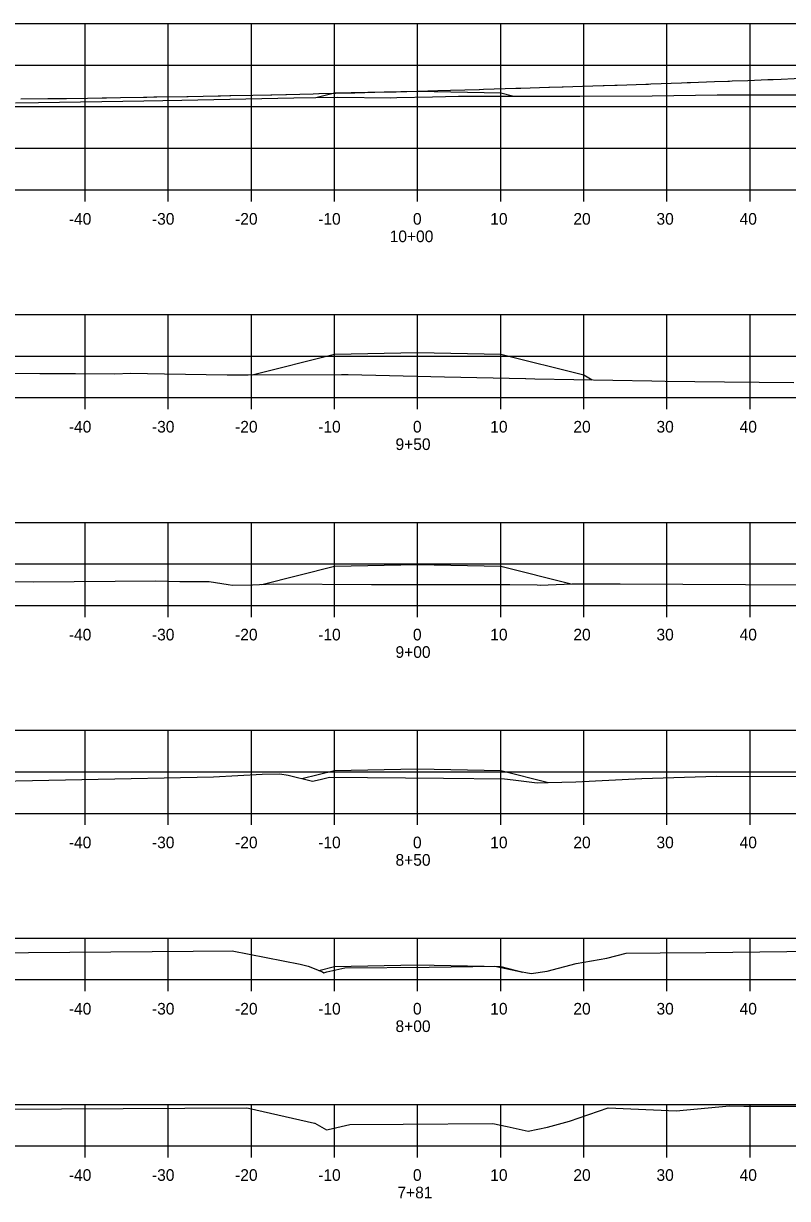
# Model space of a CAD drawing. Extents: x 1098669 to 1198896, y 698679 to 704410.
# Drawn here: x 1110733.7 to 1110825.7, y 701502.8 to 701644.1 of the extents above; entities that cross this region are included whole.
import ezdxf

# ---------------------------------------------------------------- set-up
doc = ezdxf.new("R2010")
doc.units = 0
for name, color, linetype in [('Proposed Surface', 7, 'Continuous'), ('R_Axis', 7, 'Continuous'), ('R_Axis Annot', 7, 'Continuous'), ('R_Fin Surface', 7, 'Continuous'), ('R_Grid', 7, 'Continuous')]:
    doc.layers.add(name, color=color, linetype=linetype)

msp = doc.modelspace()

# ---------------------------------------------------------------- linework, layer by layer
at = {"layer": 'Proposed Surface'}
for points in [[(1110732.78, 701634.57), (1110735.56, 701634.61), (1110748.22, 701634.82), (1110752.79, 701634.89), (1110766.27, 701635.19), (1110771.58, 701635.26), (1110777.92, 701635.2), (1110778.68, 701635.23), (1110782.94, 701635.31), (1110784.51, 701635.36), (1110786.08, 701635.39), (1110800.69, 701635.4), (1110809.37, 701635.44), (1110817.22, 701635.54), (1110827.92, 701635.53)], [(1110730.48, 701602.06), (1110735.69, 701602.04), (1110740, 701602.04), (1110744.73, 701602.01), (1110746.62, 701602.06), (1110750.72, 701602), (1110758.26, 701601.87), (1110760.79, 701601.89), (1110772.02, 701601.92), (1110772.62, 701601.92), (1110772.79, 701601.93), (1110784.41, 701601.64), (1110794.15, 701601.42), (1110794.19, 701601.42), (1110795.28, 701601.39), (1110809.35, 701601.16), (1110810.93, 701601.11), (1110818.1, 701601.03), (1110826.42, 701600.95)], [(1110727.68, 701577.01), (1110734.95, 701576.99), (1110749.68, 701577.08), (1110752.54, 701577.03), (1110755.55, 701577.02), (1110756.07, 701577.01), (1110758.37, 701576.64), (1110758.89, 701576.58), (1110761.28, 701576.62), (1110763.79, 701576.72), (1110775.63, 701576.64), (1110792.24, 701576.64), (1110795.54, 701576.61), (1110795.89, 701576.57), (1110799.77, 701576.74), (1110800.16, 701576.74), (1110805.54, 701576.75), (1110828.16, 701576.6)], [(1110724.88, 701552.88), (1110756.59, 701553.51), (1110762.45, 701553.84), (1110764.58, 701553.88), (1110765.57, 701553.71), (1110768.53, 701553), (1110769.44, 701553.21), (1110770.57, 701553.5), (1110784.28, 701553.37), (1110791.63, 701553.29), (1110792.67, 701553.18), (1110795.53, 701552.8), (1110796.84, 701552.85), (1110800.19, 701552.92), (1110808.12, 701553.34), (1110817.14, 701553.61), (1110838.07, 701553.53)], [(1110719.46, 701532.28), (1110754.17, 701532.55), (1110758.84, 701532.58), (1110767.03, 701530.99), (1110768.01, 701530.77), (1110769.7, 701530.05), (1110769.86, 701529.95), (1110770.25, 701530.05), (1110772.42, 701530.54), (1110782.55, 701530.62), (1110790.44, 701530.74), (1110793.08, 701530.17), (1110794.83, 701529.85), (1110796.73, 701530.16), (1110800.25, 701531.09), (1110803.92, 701531.73), (1110806.26, 701532.32), (1110810.35, 701532.36), (1110815.83, 701532.41), (1110825.58, 701532.51), (1110837.52, 701532.63)], [(1110723.44, 701513.53), (1110760.56, 701513.71), (1110760.83, 701513.66), (1110768.77, 701511.86), (1110768.81, 701511.85), (1110770.21, 701511.05), (1110770.4, 701511.09), (1110772.99, 701511.71), (1110779.41, 701511.74), (1110790.23, 701511.82), (1110791.94, 701511.45), (1110794.45, 701510.89), (1110796.78, 701511.4), (1110799.45, 701512.11), (1110804.08, 701513.7), (1110812.26, 701513.35), (1110818.69, 701513.94), (1110820.41, 701513.93), (1110832.6, 701513.91)]]:
    msp.add_lwpolyline(points, dxfattribs=at)
at = {"layer": 'R_Axis'}
for p, q in [((1110641.16, 701624.13), (1110921.16, 701624.13)), ((1110741.16, 701622.73), (1110741.16, 701624.13)), ((1110751.16, 701622.73), (1110751.16, 701624.13)), ((1110761.16, 701622.73), (1110761.16, 701624.13)), ((1110771.16, 701622.73), (1110771.16, 701624.13)), ((1110781.16, 701622.73), (1110781.16, 701624.13)), ((1110791.16, 701622.73), (1110791.16, 701624.13)), ((1110801.16, 701622.73), (1110801.16, 701624.13)), ((1110811.16, 701622.73), (1110811.16, 701624.13)), ((1110821.16, 701622.73), (1110821.16, 701624.13)), ((1110641.16, 701599.13), (1110921.16, 701599.13)), ((1110741.16, 701597.73), (1110741.16, 701599.13)), ((1110751.16, 701597.73), (1110751.16, 701599.13)), ((1110761.16, 701597.73), (1110761.16, 701599.13)), ((1110771.16, 701597.73), (1110771.16, 701599.13)), ((1110781.16, 701597.73), (1110781.16, 701599.13)), ((1110791.16, 701597.73), (1110791.16, 701599.13)), ((1110801.16, 701597.73), (1110801.16, 701599.13)), ((1110811.16, 701597.73), (1110811.16, 701599.13)), ((1110821.16, 701597.73), (1110821.16, 701599.13)), ((1110641.16, 701574.13), (1110921.16, 701574.13)), ((1110741.16, 701572.73), (1110741.16, 701574.13)), ((1110751.16, 701572.73), (1110751.16, 701574.13)), ((1110761.16, 701572.73), (1110761.16, 701574.13)), ((1110771.16, 701572.73), (1110771.16, 701574.13)), ((1110781.16, 701572.73), (1110781.16, 701574.13)), ((1110791.16, 701572.73), (1110791.16, 701574.13)), ((1110801.16, 701572.73), (1110801.16, 701574.13)), ((1110811.16, 701572.73), (1110811.16, 701574.13)), ((1110821.16, 701572.73), (1110821.16, 701574.13)), ((1110641.16, 701549.13), (1110921.16, 701549.13)), ((1110741.16, 701547.73), (1110741.16, 701549.13)), ((1110751.16, 701547.73), (1110751.16, 701549.13)), ((1110761.16, 701547.73), (1110761.16, 701549.13)), ((1110771.16, 701547.73), (1110771.16, 701549.13)), ((1110781.16, 701547.73), (1110781.16, 701549.13)), ((1110791.16, 701547.73), (1110791.16, 701549.13)), ((1110801.16, 701547.73), (1110801.16, 701549.13)), ((1110811.16, 701547.73), (1110811.16, 701549.13)), ((1110821.16, 701547.73), (1110821.16, 701549.13)), ((1110641.16, 701529.13), (1110921.16, 701529.13)), ((1110741.16, 701527.73), (1110741.16, 701529.13)), ((1110751.16, 701527.73), (1110751.16, 701529.13)), ((1110761.16, 701527.73), (1110761.16, 701529.13)), ((1110771.16, 701527.73), (1110771.16, 701529.13)), ((1110781.16, 701527.73), (1110781.16, 701529.13)), ((1110791.16, 701527.73), (1110791.16, 701529.13)), ((1110801.16, 701527.73), (1110801.16, 701529.13)), ((1110811.16, 701527.73), (1110811.16, 701529.13)), ((1110821.16, 701527.73), (1110821.16, 701529.13)), ((1110641.16, 701509.13), (1110921.16, 701509.13)), ((1110741.16, 701507.73), (1110741.16, 701509.13)), ((1110751.16, 701507.73), (1110751.16, 701509.13)), ((1110761.16, 701507.73), (1110761.16, 701509.13)), ((1110771.16, 701507.73), (1110771.16, 701509.13)), ((1110781.16, 701507.73), (1110781.16, 701509.13)), ((1110791.16, 701507.73), (1110791.16, 701509.13)), ((1110801.16, 701507.73), (1110801.16, 701509.13)), ((1110811.16, 701507.73), (1110811.16, 701509.13)), ((1110821.16, 701507.73), (1110821.16, 701509.13))]:
    msp.add_line(p, q, dxfattribs=at)
at = {"layer": 'R_Fin Surface'}
for points in [[(1110733.41, 701635.05), (1110736.68, 701635.09), (1110737.43, 701635.1), (1110738.24, 701635.11), (1110738.42, 701635.11), (1110738.93, 701635.12), (1110741.43, 701635.16), (1110743.19, 701635.19), (1110743.47, 701635.19), (1110743.73, 701635.19), (1110745.43, 701635.22), (1110748.19, 701635.27), (1110748.51, 701635.27), (1110748.6, 701635.27), (1110749.42, 701635.29), (1110749.79, 701635.29), (1110753.4, 701635.36), (1110753.53, 701635.36), (1110753.54, 701635.36), (1110757.17, 701635.43), (1110757.38, 701635.44), (1110757.44, 701635.44), (1110758.56, 701635.46), (1110758.7, 701635.46), (1110761.35, 701635.52), (1110763.51, 701635.56), (1110763.58, 701635.56), (1110763.63, 701635.56), (1110765.32, 701635.6), (1110765.39, 701635.6), (1110768.58, 701635.68), (1110769.27, 701635.69), (1110769.28, 701635.69), (1110769.33, 701635.69), (1110773.24, 701635.79), (1110773.58, 701635.8), (1110773.59, 701635.8), (1110777.2, 701635.89), (1110777.2, 701635.89), (1110777.21, 701635.89), (1110778.59, 701635.92), (1110781.16, 701635.99), (1110783.59, 701636.06), (1110783.59, 701636.06), (1110783.59, 701636.06), (1110785.12, 701636.1), (1110788.57, 701636.2), (1110788.59, 701636.2), (1110788.59, 701636.2), (1110789.08, 701636.21), (1110792.99, 701636.33), (1110793.04, 701636.33), (1110793.05, 701636.33), (1110793.59, 701636.35), (1110796.93, 701636.45), (1110797.01, 701636.46), (1110798.55, 701636.51), (1110798.6, 701636.51), (1110798.67, 701636.51), (1110800.98, 701636.58), (1110803.49, 701636.67), (1110803.61, 701636.67), (1110804.88, 701636.71), (1110804.95, 701636.72), (1110805.15, 701636.72), (1110808.63, 701636.84), (1110808.9, 701636.85), (1110808.93, 701636.85), (1110809.22, 701636.86), (1110812.91, 701637), (1110813.59, 701637.02), (1110813.66, 701637.02), (1110813.99, 701637.04), (1110816.9, 701637.14), (1110818.47, 701637.2), (1110818.7, 701637.21), (1110819, 701637.22), (1110820.89, 701637.29), (1110823.28, 701637.39), (1110823.76, 701637.41), (1110823.95, 701637.41), (1110824.9, 701637.45), (1110828.01, 701637.58)], [(1110768.9, 701635.23), (1110771.16, 701635.79), (1110781.16, 701635.99), (1110791.16, 701635.79), (1110792.75, 701635.39)], [(1110761.27, 701601.89), (1110771.16, 701604.37), (1110781.16, 701604.57), (1110791.16, 701604.37), (1110801.16, 701601.87), (1110802.16, 701601.28)], [(1110762.42, 701576.66), (1110771.16, 701578.85), (1110781.16, 701579.05), (1110791.16, 701578.85), (1110799.63, 701576.73)], [(1110767.23, 701553.31), (1110771.16, 701554.29), (1110781.16, 701554.49), (1110791.16, 701554.29), (1110796.92, 701552.85)], [(1110769.27, 701530.23), (1110771.16, 701530.7), (1110781.16, 701530.9), (1110791.16, 701530.7), (1110793.79, 701530.04)]]:
    msp.add_lwpolyline(points, dxfattribs=at)
at = {"layer": 'R_Grid'}
for p, q in [((1110641.16, 701644.13), (1110921.16, 701644.13)), ((1110741.16, 701624.13), (1110741.16, 701644.13)), ((1110751.16, 701624.13), (1110751.16, 701644.13)), ((1110761.16, 701624.13), (1110761.16, 701644.13)), ((1110771.16, 701624.13), (1110771.16, 701644.13)), ((1110781.16, 701624.13), (1110781.16, 701644.13)), ((1110791.16, 701624.13), (1110791.16, 701644.13)), ((1110801.16, 701624.13), (1110801.16, 701644.13)), ((1110811.16, 701624.13), (1110811.16, 701644.13)), ((1110821.16, 701624.13), (1110821.16, 701644.13)), ((1110641.16, 701639.13), (1110921.16, 701639.13)), ((1110641.16, 701634.13), (1110921.16, 701634.13)), ((1110641.16, 701629.13), (1110921.16, 701629.13)), ((1110641.16, 701624.13), (1110921.16, 701624.13)), ((1110641.16, 701609.13), (1110921.16, 701609.13)), ((1110741.16, 701599.13), (1110741.16, 701609.13)), ((1110751.16, 701599.13), (1110751.16, 701609.13)), ((1110761.16, 701599.13), (1110761.16, 701609.13)), ((1110771.16, 701599.13), (1110771.16, 701609.13)), ((1110781.16, 701599.13), (1110781.16, 701609.13)), ((1110791.16, 701599.13), (1110791.16, 701609.13)), ((1110801.16, 701599.13), (1110801.16, 701609.13)), ((1110811.16, 701599.13), (1110811.16, 701609.13)), ((1110821.16, 701599.13), (1110821.16, 701609.13)), ((1110641.16, 701604.13), (1110921.16, 701604.13)), ((1110641.16, 701599.13), (1110921.16, 701599.13)), ((1110641.16, 701584.13), (1110921.16, 701584.13)), ((1110741.16, 701574.13), (1110741.16, 701584.13)), ((1110751.16, 701574.13), (1110751.16, 701584.13)), ((1110761.16, 701574.13), (1110761.16, 701584.13)), ((1110771.16, 701574.13), (1110771.16, 701584.13)), ((1110781.16, 701574.13), (1110781.16, 701584.13)), ((1110791.16, 701574.13), (1110791.16, 701584.13)), ((1110801.16, 701574.13), (1110801.16, 701584.13)), ((1110811.16, 701574.13), (1110811.16, 701584.13)), ((1110821.16, 701574.13), (1110821.16, 701584.13)), ((1110641.16, 701579.13), (1110921.16, 701579.13)), ((1110641.16, 701574.13), (1110921.16, 701574.13)), ((1110641.16, 701559.13), (1110921.16, 701559.13)), ((1110741.16, 701549.13), (1110741.16, 701559.13)), ((1110751.16, 701549.13), (1110751.16, 701559.13)), ((1110761.16, 701549.13), (1110761.16, 701559.13)), ((1110771.16, 701549.13), (1110771.16, 701559.13)), ((1110781.16, 701549.13), (1110781.16, 701559.13)), ((1110791.16, 701549.13), (1110791.16, 701559.13)), ((1110801.16, 701549.13), (1110801.16, 701559.13)), ((1110811.16, 701549.13), (1110811.16, 701559.13)), ((1110821.16, 701549.13), (1110821.16, 701559.13)), ((1110641.16, 701554.13), (1110921.16, 701554.13)), ((1110641.16, 701549.13), (1110921.16, 701549.13)), ((1110641.16, 701534.13), (1110921.16, 701534.13)), ((1110741.16, 701529.13), (1110741.16, 701534.13)), ((1110751.16, 701529.13), (1110751.16, 701534.13)), ((1110761.16, 701529.13), (1110761.16, 701534.13)), ((1110771.16, 701529.13), (1110771.16, 701534.13)), ((1110781.16, 701529.13), (1110781.16, 701534.13)), ((1110791.16, 701529.13), (1110791.16, 701534.13)), ((1110801.16, 701529.13), (1110801.16, 701534.13)), ((1110811.16, 701529.13), (1110811.16, 701534.13)), ((1110821.16, 701529.13), (1110821.16, 701534.13)), ((1110641.16, 701529.13), (1110921.16, 701529.13)), ((1110641.16, 701514.13), (1110921.16, 701514.13)), ((1110741.16, 701509.13), (1110741.16, 701514.13)), ((1110751.16, 701509.13), (1110751.16, 701514.13)), ((1110761.16, 701509.13), (1110761.16, 701514.13)), ((1110771.16, 701509.13), (1110771.16, 701514.13)), ((1110781.16, 701509.13), (1110781.16, 701514.13)), ((1110791.16, 701509.13), (1110791.16, 701514.13)), ((1110801.16, 701509.13), (1110801.16, 701514.13)), ((1110811.16, 701509.13), (1110811.16, 701514.13)), ((1110821.16, 701509.13), (1110821.16, 701514.13)), ((1110641.16, 701509.13), (1110921.16, 701509.13))]:
    msp.add_line(p, q, dxfattribs=at)

# ---------------------------------------------------------------- texts
at = {"layer": 'R_Axis Annot'}
for s, p in [('-40', (1110739.2, 701619.93)), ('-30', (1110749.2, 701619.93)), ('-20', (1110759.2, 701619.93)), ('-10', (1110769.2, 701619.93)), ('0', (1110780.6, 701619.93)), ('10', (1110789.9, 701619.93)), ('20', (1110799.9, 701619.93)), ('30', (1110809.9, 701619.93)), ('40', (1110819.9, 701619.93)), ('10+00', (1110777.8, 701617.83)), ('-40', (1110739.2, 701594.93)), ('-30', (1110749.2, 701594.93)), ('-20', (1110759.2, 701594.93)), ('-10', (1110769.2, 701594.93)), ('0', (1110780.6, 701594.93)), ('10', (1110789.9, 701594.93)), ('20', (1110799.9, 701594.93)), ('30', (1110809.9, 701594.93)), ('40', (1110819.9, 701594.93)), ('9+50', (1110778.5, 701592.83)), ('-40', (1110739.2, 701569.93)), ('-30', (1110749.2, 701569.93)), ('-20', (1110759.2, 701569.93)), ('-10', (1110769.2, 701569.93)), ('0', (1110780.6, 701569.93)), ('10', (1110789.9, 701569.93)), ('20', (1110799.9, 701569.93)), ('30', (1110809.9, 701569.93)), ('40', (1110819.9, 701569.93)), ('9+00', (1110778.5, 701567.83)), ('-40', (1110739.2, 701544.93)), ('-30', (1110749.2, 701544.93)), ('-20', (1110759.2, 701544.93)), ('-10', (1110769.2, 701544.93)), ('0', (1110780.6, 701544.93)), ('10', (1110789.9, 701544.93)), ('20', (1110799.9, 701544.93)), ('30', (1110809.9, 701544.93)), ('40', (1110819.9, 701544.93)), ('8+50', (1110778.5, 701542.83)), ('-40', (1110739.2, 701524.93)), ('-30', (1110749.2, 701524.93)), ('-20', (1110759.2, 701524.93)), ('-10', (1110769.2, 701524.93)), ('0', (1110780.6, 701524.93)), ('10', (1110789.9, 701524.93)), ('20', (1110799.9, 701524.93)), ('30', (1110809.9, 701524.93)), ('40', (1110819.9, 701524.93)), ('8+00', (1110778.5, 701522.83)), ('-40', (1110739.2, 701504.93)), ('-30', (1110749.2, 701504.93)), ('-20', (1110759.2, 701504.93)), ('-10', (1110769.2, 701504.93)), ('0', (1110780.6, 701504.93)), ('10', (1110789.9, 701504.93)), ('20', (1110799.9, 701504.93)), ('30', (1110809.9, 701504.93)), ('40', (1110819.9, 701504.93)), ('7+81', (1110778.73, 701502.83))]:
    msp.add_text(s, height=1.4, dxfattribs=at).set_placement(p)

doc.saveas('drawing.dxf')
